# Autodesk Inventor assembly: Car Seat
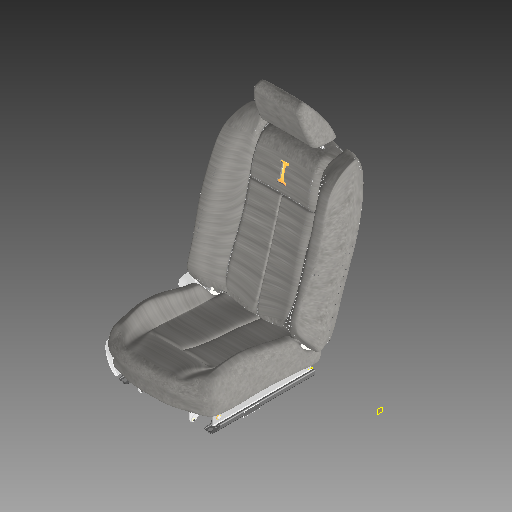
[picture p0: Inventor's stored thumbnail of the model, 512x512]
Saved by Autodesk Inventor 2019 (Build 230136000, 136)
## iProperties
Company: Autodesk Inc.
Created: 2007-12
Part Number: Car Seat
Document SubType Name: Assembly
Designer: Autodesk Inc.
Mass: 63194.6 g
Surface Area: 75615.4 cm^2
Volume: 49572.4 cm^3
Density: 1.27479 g/cm^3
Description: SUPER CAR DRIVER SEAT 1000
Author: Inventor
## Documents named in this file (20)
- C:\TEMP\Car Seat\Workspace\Car Seat.iam
- C:\TEMP\Car Seat\Workspace\Handle.ipt
- C:\TEMP\Car Seat\Workspace\Spring Holder Pin.ipt
- C:\TEMP\Car Seat\Workspace\Side Handle Pivot Pin.ipt
- C:\TEMP\Car Seat\Workspace\Bell Crank Side Handle.ipt
- C:\TEMP\Car Seat\Workspace\Rear Pivot Lock Plate.ipt
- C:\TEMP\Car Seat\Workspace\Rear Tilt Spring.ipt
- C:\TEMP\Car Seat\Workspace\Wire Holder A.ipt
- C:\TEMP\Car Seat\Workspace\Wire Holder B.ipt
- C:\TEMP\Car Seat\Workspace\Side Link Bar.ipt
- C:\TEMP\Car Seat\Workspace\Side Cover.ipt
- C:\TEMP\Car Seat\Workspace\Power Switch Control.ipt
- C:\TEMP\Car Seat\Workspace\Power Switch Tab.ipt
- C:\TEMP\Car Seat\Workspace\Control Switch Connector.ipt
- C:\TEMP\Car Seat\Workspace\Upper Seat Cover.ipt
- C:\TEMP\Car Seat\Workspace\Lower Seat Cushion.ipt
- C:\TEMP\Car Seat\Workspace\Upper Seat Cushion.ipt
- C:\TEMP\Car Seat\Workspace\Lower Full Assembly.iam
- C:\TEMP\Car Seat\Workspace\Back Frame Main Assembly.iam
- C:\TEMP\Car Seat\Workspace\Headrest.iam
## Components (19 placed, 19 different names)
1. Lower Full Assembly:1 [sub-assembly] — Flush:1, Insert:1, Insert:3, Mate:6, Mate:25, Angle:4, Flush:4, Flush:5, Flush:6
2. Back Frame Main Assembly:1 [sub-assembly] — Flush:1, Mate:7, Angle:1, Mate:11, Flush:2, Mate:18, Mate:19, Mate:25, Angle:4
3. Headrest:1 [sub-assembly] — Flush:2, Mate:18, Mate:19
4. Spring Holder Pin:1 — Insert:1, Tangent:2, Tangent:3
5. Side Handle Pivot Pin:1 — Insert:3, Mate:4, Mate:5, Mate:26, Mate:27
6. Bell Crank Side Handle:1 — Mate:4, Mate:5, Insert:4, Angle:5
7. Rear Pivot Lock Plate:1 — Mate:6, Mate:7, Angle:1, Insert:5
8. Rear Tilt Spring:1 — Mate:11, Tangent:2, Tangent:3
9. Wire Holder A:1 — Insert:4, Mate:14, Mate:15
10. Wire Holder B:1 — Insert:5, Mate:12, Mate:13
11. Side Link Bar:1 — Mate:12, Mate:13, Mate:14, Mate:15
12. Side Cover:1 — Flush:4, Flush:5, Flush:6, Mate:28, Mate:29, Mate:30
13. Handle:1 — Mate:26, Mate:27, Angle:5
14. Power Switch Control:1 — Mate:28, Mate:29, Mate:30, Insert:6, Mate:31, Mate:32, Mate:33, Mate:34
15. Power Switch Tab:1 — Insert:6, Mate:31
16. Control Switch Connector:1 — Mate:32, Mate:33, Mate:34
17. Upper Seat Cover:1 — Flush:7, Flush:9, Flush:10, Flush:11
18. Lower Seat Cushion:1 — Flush:8
19. Upper Seat Cushion:1 — Flush:9, Flush:10, Flush:11
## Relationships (41: Mate 21, Flush 10, Insert 5, Angle 3, Tangent 2)
- Flush:1: Lower Full Assembly:1 ↔ Back Frame Main Assembly:1
- Insert:1: Lower Full Assembly:1 ↔ Spring Holder Pin:1
- Insert:3: Lower Full Assembly:1 ↔ Side Handle Pivot Pin:1
- Mate:4: Side Handle Pivot Pin:1 ↔ Bell Crank Side Handle:1
- Mate:5: Side Handle Pivot Pin:1 ↔ Bell Crank Side Handle:1
- Mate:6: Lower Full Assembly:1 ↔ Rear Pivot Lock Plate:1
- Mate:7: Back Frame Main Assembly:1 ↔ Rear Pivot Lock Plate:1
- Angle:1: Back Frame Main Assembly:1 ↔ Rear Pivot Lock Plate:1
- Mate:11: Back Frame Main Assembly:1 ↔ Rear Tilt Spring:1
- Tangent:2: Spring Holder Pin:1 ↔ Rear Tilt Spring:1
- Insert:4: Bell Crank Side Handle:1 ↔ Wire Holder A:1
- Insert:5: Rear Pivot Lock Plate:1 ↔ Wire Holder B:1
- Mate:12: Wire Holder B:1 ↔ Side Link Bar:1
- Mate:13: Wire Holder B:1 ↔ Side Link Bar:1
- Mate:14: Wire Holder A:1 ↔ Side Link Bar:1
- Mate:15: Wire Holder A:1 ↔ Side Link Bar:1
- Flush:2: Back Frame Main Assembly:1 ↔ Headrest:1
- Mate:18: Back Frame Main Assembly:1 ↔ Headrest:1
- Mate:19: Back Frame Main Assembly:1 ↔ Headrest:1
- Mate:25: Lower Full Assembly:1 ↔ Back Frame Main Assembly:1
- Tangent:3: Spring Holder Pin:1 ↔ Rear Tilt Spring:1
- Angle:4: Lower Full Assembly:1 ↔ Back Frame Main Assembly:1
- Flush:4: Lower Full Assembly:1 ↔ Side Cover:1
- Flush:5: Lower Full Assembly:1 ↔ Side Cover:1
- Flush:6: Lower Full Assembly:1 ↔ Side Cover:1
- Mate:26: Side Handle Pivot Pin:1 ↔ Handle:1
- Mate:27: Side Handle Pivot Pin:1 ↔ Handle:1
- Mate:28: Side Cover:1 ↔ Power Switch Control:1
- Mate:29: Side Cover:1 ↔ Power Switch Control:1
- Mate:30: Side Cover:1 ↔ Power Switch Control:1
- Insert:6: Power Switch Control:1 ↔ Power Switch Tab:1
- Mate:31: Power Switch Control:1 ↔ Power Switch Tab:1
- Angle:5: Bell Crank Side Handle:1 ↔ Handle:1
- Mate:32: Power Switch Control:1 ↔ Control Switch Connector:1
- Mate:33: Power Switch Control:1 ↔ Control Switch Connector:1
- Mate:34: Power Switch Control:1 ↔ Control Switch Connector:1
- Flush:7: Upper Seat Cover:1
- Flush:8: Lower Seat Cushion:1
- Flush:9: Upper Seat Cover:1 ↔ Upper Seat Cushion:1
- Flush:10: Upper Seat Cover:1 ↔ Upper Seat Cushion:1
- Flush:11: Upper Seat Cover:1 ↔ Upper Seat Cushion:1
